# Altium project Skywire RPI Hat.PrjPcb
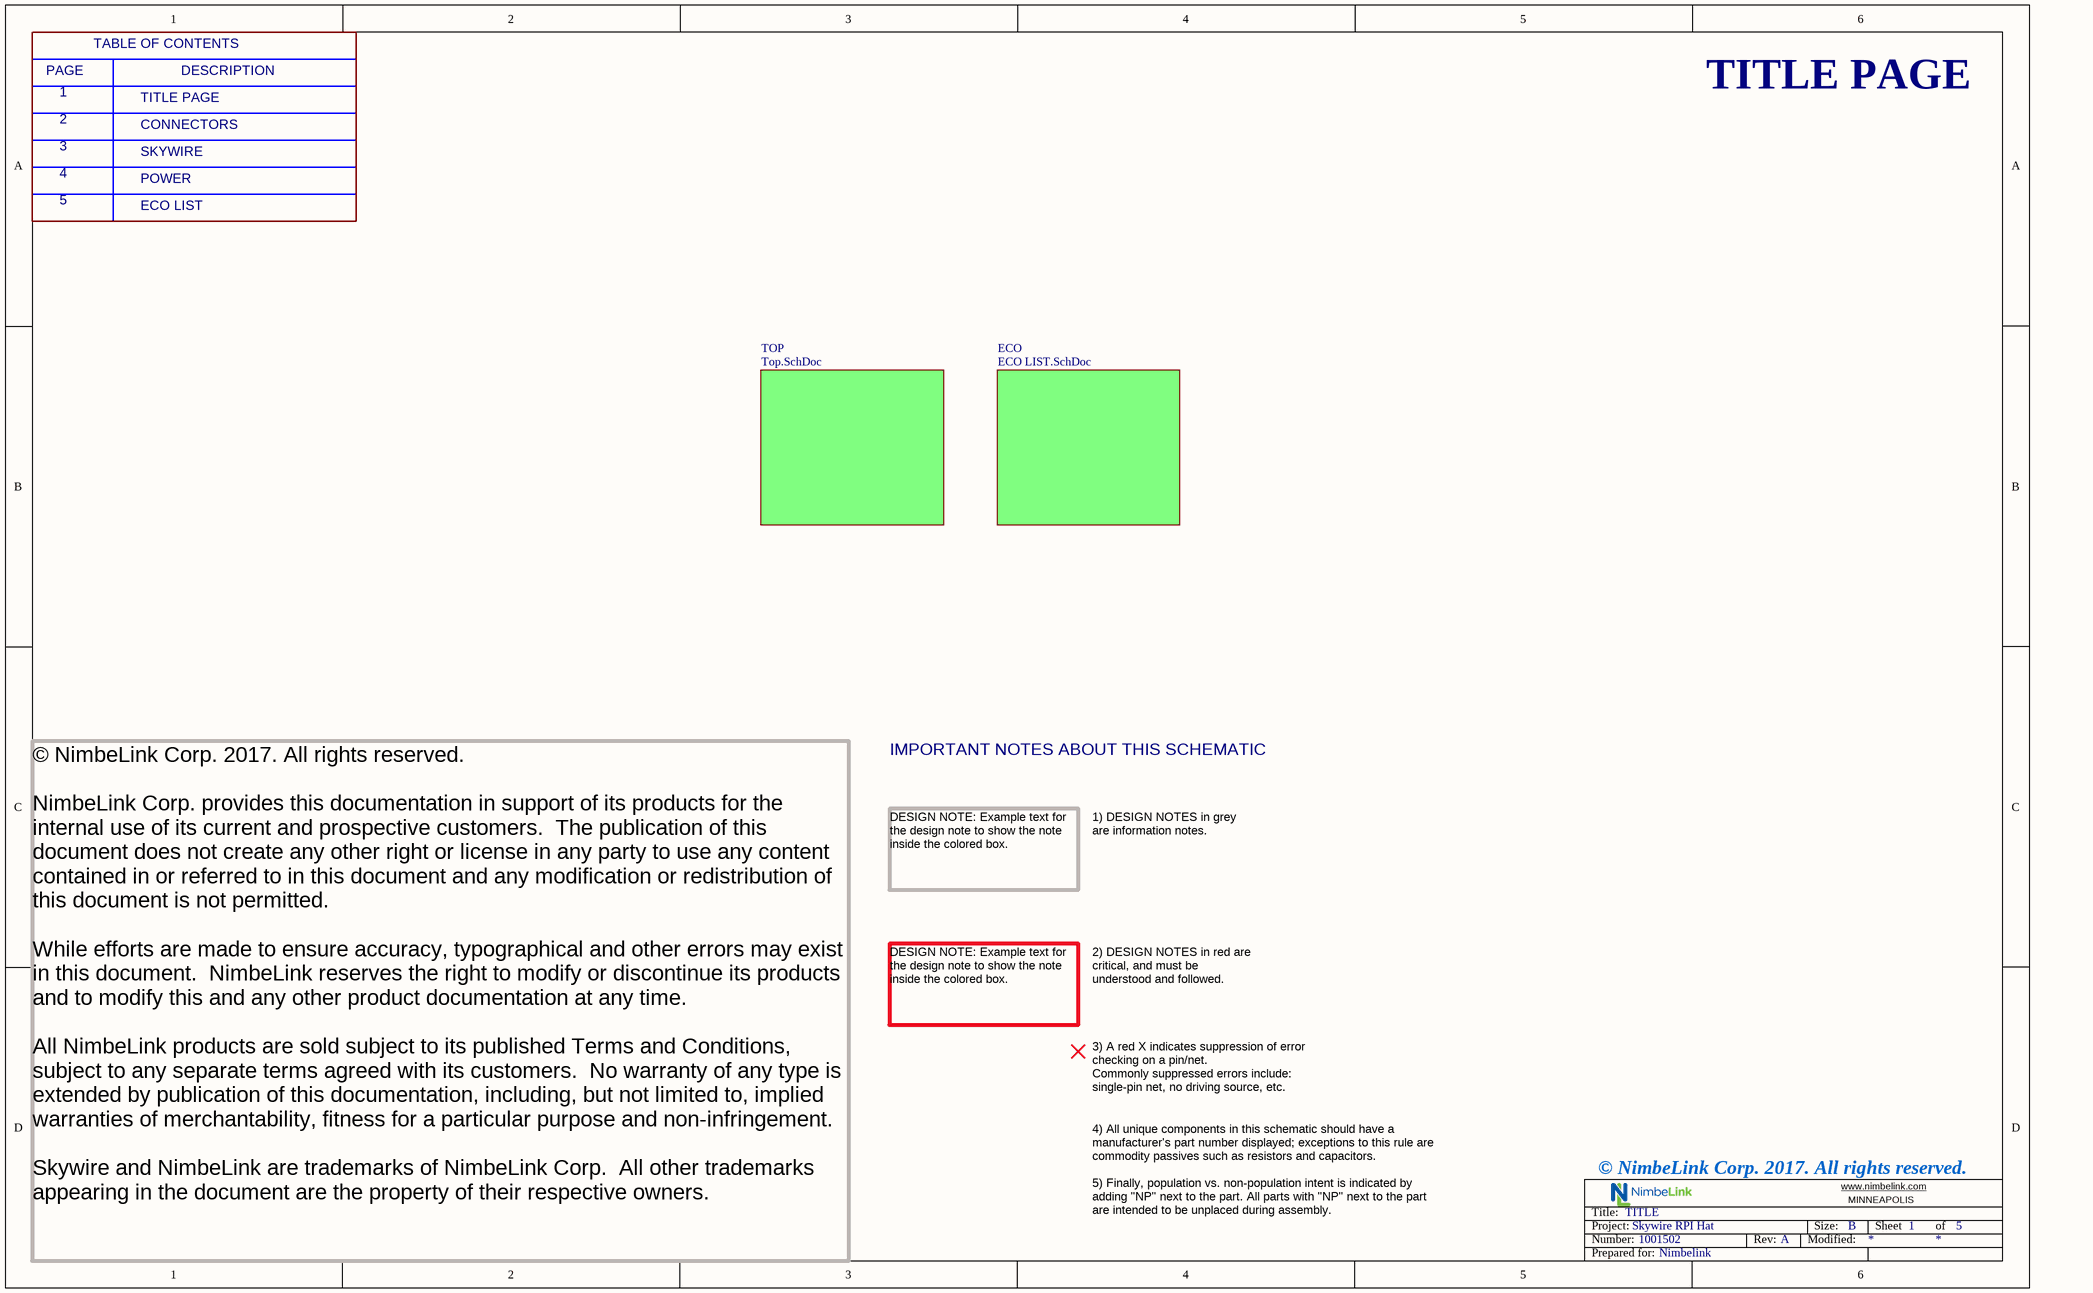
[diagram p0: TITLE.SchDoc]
NL_BILLING_CODE: Skywire RPI Hat; NL_SCH_PN: 1001502; NL_SCH_REV: A; NL_VERBOSE_CUST_NAME: Nimbelink
5 sheets, 73 parts. Net scope: flat (ports and power ports of the same name join across sheets).
Board file: RPI_Hat.PcbDoc
Sheets:
  TITLE.SchDoc
    TOP = Top.SchDoc
      Skywire = Skywire.SchDoc
      Power = Power.SchDoc
    ECO = ECO LIST.SchDoc

## Sheet TITLE.SchDoc: TITLE
size B; DocumentNumber: 1; SheetNumber: 1; SheetTotal: 5

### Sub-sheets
ECO = ECO LIST.SchDoc: no entries
TOP = Top.SchDoc: no entries

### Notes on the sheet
- PAGE
- 1
- TABLE OF CONTENTS
- TITLE PAGE
- DESCRIPTION
- 2
- 3
- CONNECTORS
- SKYWIRE
- 4
- 5
- ECO LIST
- POWER
- IMPORTANT NOTES ABOUT THIS SCHEMATIC
- DESIGN NOTE: Example text for the design note to show the note inside the colored box.
- 1) DESIGN NOTES in grey are information notes.
- 2) DESIGN NOTES in red are critical, and must be understood and followed.
- 3) A red X indicates suppression of error checking on a pin/net.
  Commonly suppressed errors include: single-pin net, no driving source, etc.
- © NimbeLink Corp. 2017. All rights reserved.
- 4) All unique components in this schematic should have a manufacturer's part number displayed; exceptions to this rule are commodity passives such as resistors and capacitors.
  5) Finally, population vs. non-population intent is indicated by adding "NP" next to the part. All parts with "NP" next to the part are intended to be unplaced during assembly.
- © NimbeLink Corp. 2017. All rights reserved.
  NimbeLink Corp. provides this documentation in support of its products for the internal use of its current and prospective customers.  The publication of this document does not create any other right or license in any party to use any content contained in or referred to in this document and any modification or redistribution of this document is not permitted.
  While efforts are made to ensure accuracy, typographical and other errors may exist in this document.  NimbeLink reserves the right to modify or discontinue its products and to modify this and any other product documentation at any time.
  All NimbeLink products are sold subject to its published Terms and Conditions, subject to any separate terms agreed with its customers.  No warranty of any type is extended by publication of this documentation, including, but not limited to, implied warranties of merchantability, fitness for a particular purpose and non-infringement.
  Skywire and NimbeLink are trademarks of NimbeLink Corp.  All other trademarks appearing in the document are the property of their respective owners.

## Sheet Top.SchDoc: TOP
size B; DocumentNumber: 2; SheetNumber: 2; SheetTotal: 5
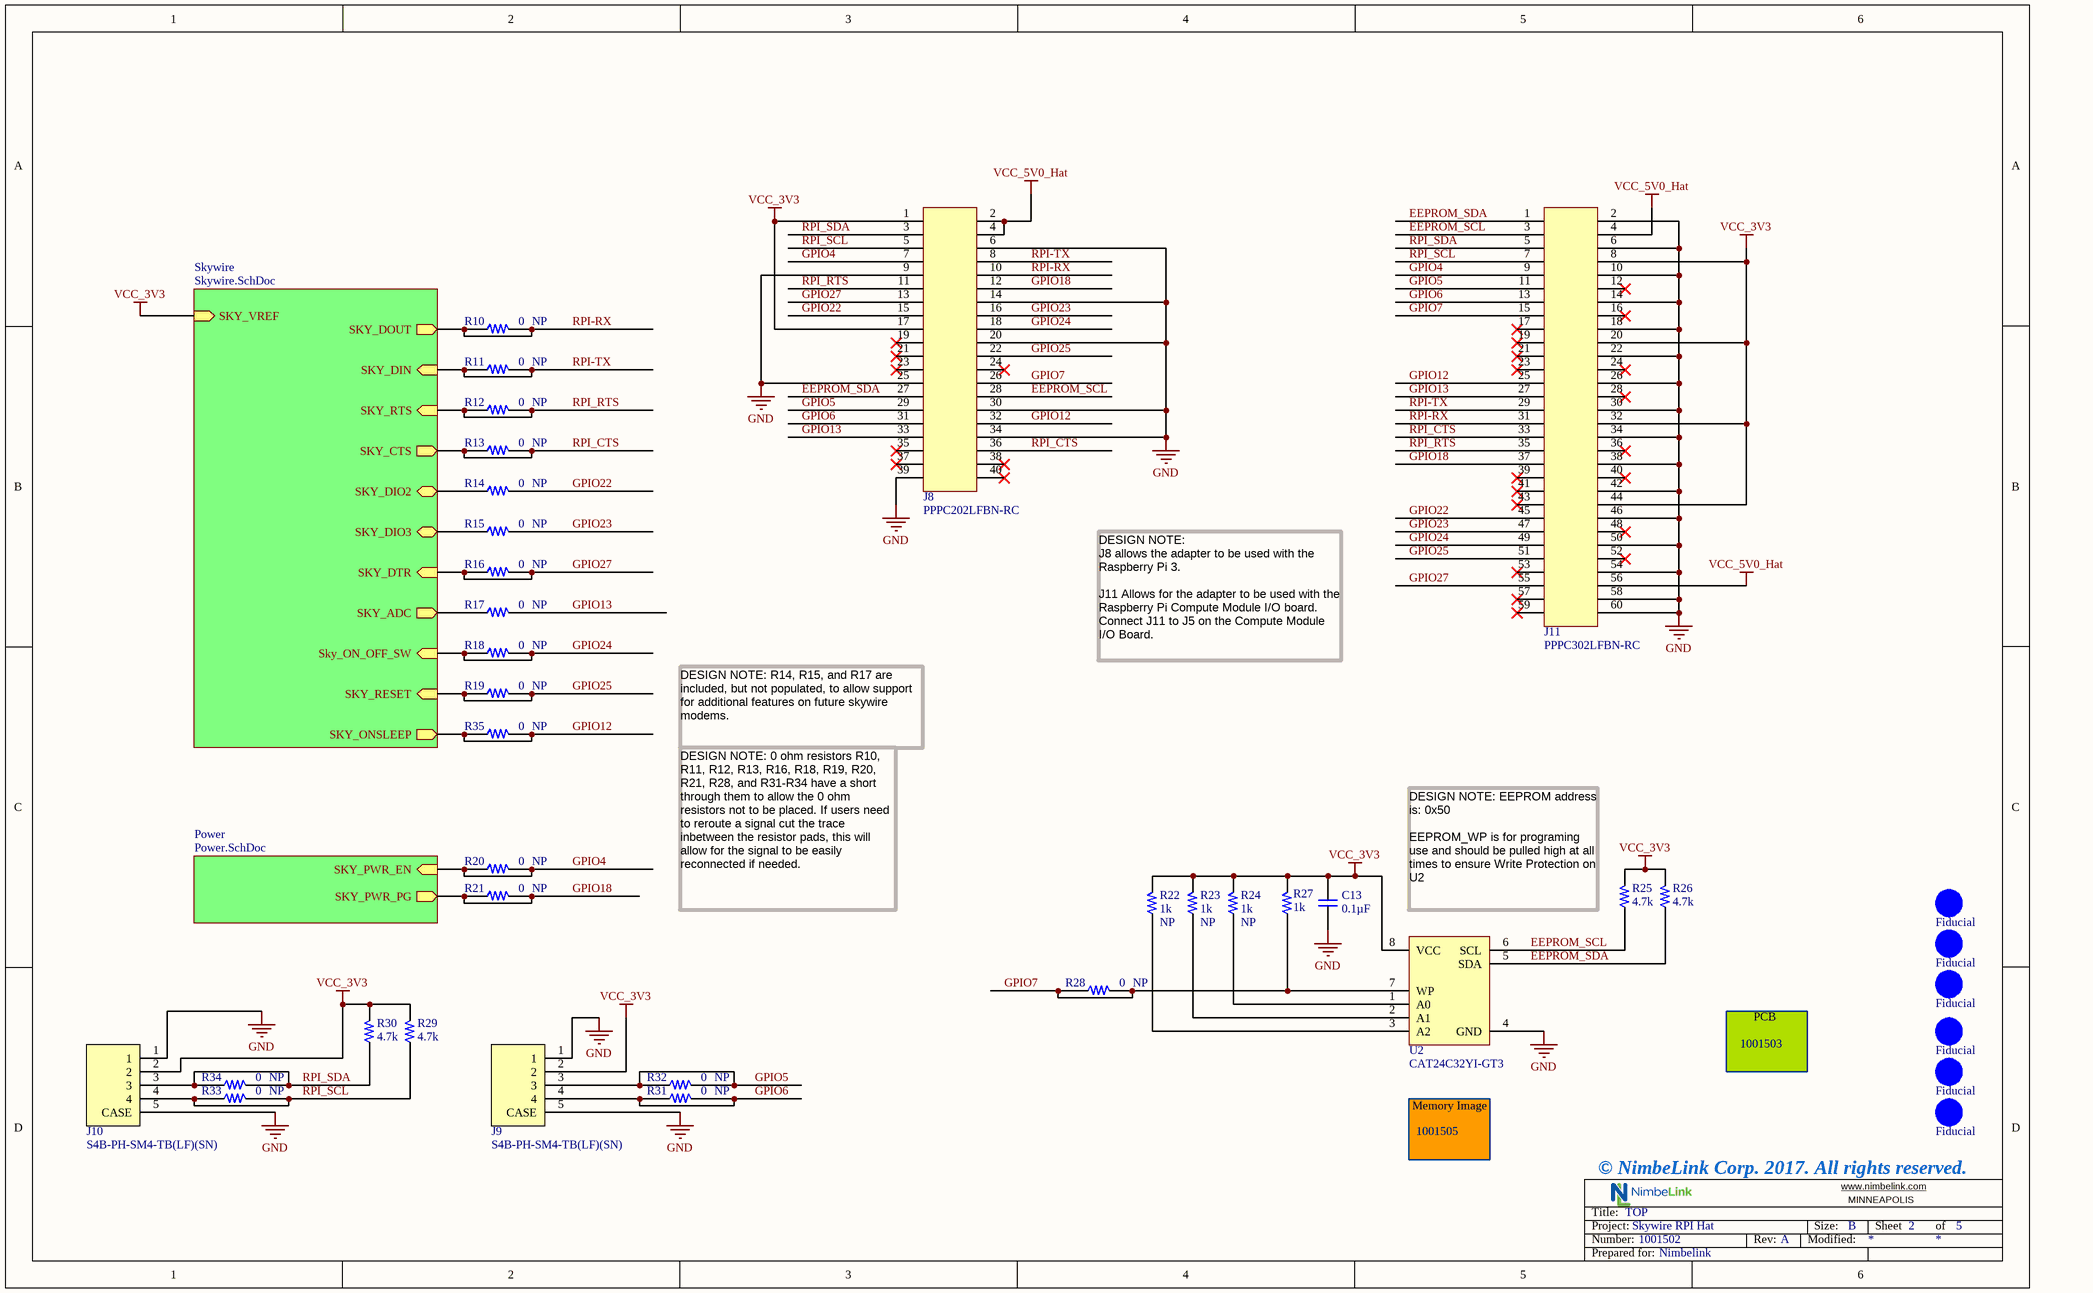
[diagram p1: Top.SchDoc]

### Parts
C13  Capacitance: 0.1µF  [0603]  (hidden comment: 1000755)
Fiducial1  Fiducial  [Fiducial 1mm]
Fiducial2  Fiducial  [Fiducial 1mm]
Fiducial3  Fiducial  [Fiducial 1mm]
Fiducial4  Fiducial  [Fiducial 1mm]
Fiducial5  Fiducial  [Fiducial 1mm]
Fiducial6  Fiducial  [Fiducial 1mm]
J8  1001252  [PPPC202LFBN-RC]  (value not drawn)
J9  1001260  [S4B-PH-SM4-TB(LF)(SN)]  (value not drawn)
J10  1001260  [S4B-PH-SM4-TB(LF)(SN)]  (value not drawn)
J11  1001253  [PPPC302LFBN-RC]  (value not drawn)
Memory_Image  Part_Number: 1001505  (hidden comment: Memory_Image)  (mechanical)
PCB  Part_Number: 1001503  (hidden comment: PCB)  (mechanical)
R10  Population: NP  [0603]  (hidden comment: 0)
R11  Population: NP  [0603]  (hidden comment: 0)
R12  Population: NP  [0603]  (hidden comment: 0)
R13  Population: NP  [0603]  (hidden comment: 0)
R14  Population: NP  [0603]  (hidden comment: 0)
R15  Population: NP  [0603]  (hidden comment: 0)
R16  Population: NP  [0603]  (hidden comment: 0)
R17  Population: NP  [0603]  (hidden comment: 0)
R18  Population: NP  [0603]  (hidden comment: 0)
R19  Population: NP  [0603]  (hidden comment: 0)
R20  Population: NP  [0603]  (hidden comment: 0)
R21  Population: NP  [0603]  (hidden comment: 0)
R22  Population: NP  Resistance_Ohms: 1k  [0603]
R23  Population: NP  Resistance_Ohms: 1k  [0603]
R24  Population: NP  Resistance_Ohms: 1k  [0603]
R25  Resistance_Ohms: 4.7k  [0603]  (hidden comment: 1000803)
R26  Resistance_Ohms: 4.7k  [0603]  (hidden comment: 1000803)
R27  Resistance_Ohms: 1k  [0603]
R28  Population: NP  [0603]  (hidden comment: 0)
R29  Resistance_Ohms: 4.7k  [0603]  (hidden comment: 1000803)
R30  Resistance_Ohms: 4.7k  [0603]  (hidden comment: 1000803)
R31  Population: NP  [0603]  (hidden comment: 0)
R32  Population: NP  [0603]  (hidden comment: 0)
R33  Population: NP  [0603]  (hidden comment: 0)
R34  Population: NP  [0603]  (hidden comment: 0)
R35  Population: NP  [0603]  (hidden comment: 0)
U2  .  [TSSOP8 4.4x3 CASE 948AL-01]  (value not drawn)

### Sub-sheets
Power = Power.SchDoc: SKY_PWR_EN (in), SKY_PWR_PG (out)
Skywire = Skywire.SchDoc: SKY_DOUT (out), SKY_DIN (in), SKY_RTS (in), SKY_CTS (out), Sky_ON_OFF_SW (in), SKY_DTR (in), SKY_VREF (in), SKY_DIO2 (bidir), SKY_DIO3 (bidir), SKY_ADC (out), SKY_RESET (in), SKY_ONSLEEP (out)

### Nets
GND: C13.2 J8.6 J8.9 J8.14 J8.20 J8.25 J8.30 J8.34 J8.39 J9.1 J9.5(CASE) J10.1 J10.5(CASE) J11.2 J11.6 J11.10 J11.14 J11.18 J11.22 J11.26 J11.30 J11.34 J11.38 J11.42 J11.46 J11.50 J11.54 J11.58 J11.60 U2.4(GND)
VCC_3V3: C13.1 J8.1 J8.17 J9.2 J10.2 J11.8 J11.20 J11.32 J11.44 R22.2 R23.2 R24.2 R25.2 R26.2 R27.2 R29.2 R30.2 U2.8(VCC) ; sheet Skywire/SKY_VREF
VCC_5V0_Hat: J8.2 J8.4 J11.4 J11.56
EEPROM_SCL: J8.28 J11.3 R25.1 U2.6(SCL)
EEPROM_SDA: J8.27 J11.1 R26.1 U2.5(SDA)
GPIO4: J8.7 J11.9 R20.1 R20.2 ; sheet Power/SKY_PWR_EN
GPIO5: J8.29 J9.3 J11.11 R32.1 R32.2
GPIO6: J8.31 J9.4 J11.13 R31.1 R31.2
GPIO7: J8.26 J11.15 R27.1 R28.1 R28.2 U2.7(WP)
GPIO12: J8.32 J11.25 R35.1 R35.2 ; sheet Skywire/SKY_ONSLEEP
GPIO13: J8.33 J11.27 R17.2
GPIO18: J8.12 J11.37 R21.1 R21.2 ; sheet Power/SKY_PWR_PG
GPIO22: J8.15 J11.45 R14.2
GPIO23: J8.16 J11.47 R15.2
GPIO24: J8.18 J11.49 R18.1 R18.2 ; sheet Skywire/Sky_ON_OFF_SW
GPIO25: J8.22 J11.51 R19.1 R19.2 ; sheet Skywire/SKY_RESET
GPIO27: J8.13 J11.55 R16.1 R16.2 ; sheet Skywire/SKY_DTR
RPI-RX: J8.10 J11.31 R10.1 R10.2 ; sheet Skywire/SKY_DOUT
RPI-TX: J8.8 J11.29 R11.1 R11.2 ; sheet Skywire/SKY_DIN
RPI_CTS: J8.36 J11.33 R13.1 R13.2 ; sheet Skywire/SKY_CTS
RPI_RTS: J8.11 J11.35 R12.1 R12.2 ; sheet Skywire/SKY_RTS
RPI_SCL: J8.5 J10.4 J11.7 R29.1 R33.1 R33.2
RPI_SDA: J8.3 J10.3 J11.5 R30.1 R34.1 R34.2
NetR14_1: R14.1 ; sheet Skywire/SKY_DIO2
NetR15_1: R15.1 ; sheet Skywire/SKY_DIO3
NetR17_1: R17.1 ; sheet Skywire/SKY_ADC
NetR22_1: R22.1 U2.3(A2)
NetR23_1: R23.1 U2.2(A1)
NetR24_1: R24.1 U2.1(A0)

Not connected (* = marked no-connect by the designer): J8 19* 21* 23* 24* 35* 37* 38* 40*; J11 12* 16* 17* 19* 21* 23* 24* 28* 36* 39* 40* 41* 43* 48* 52* 53* 57* 59*

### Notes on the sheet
- DESIGN NOTE:
  J8 allows the adapter to be used with the Raspberry Pi 3.
  J11 Allows for the adapter to be used with the Raspberry Pi Compute Module I/O board. Connect J11 to J5 on the Compute Module I/O Board.
- DESIGN NOTE: R14, R15, and R17 are included, but not populated, to allow support for additional features on future skywire modems.
- DESIGN NOTE: 0 ohm resistors R10, R11, R12, R13, R16, R18, R19, R20, R21, R28, and R31-R34 have a short through them to allow the 0 ohm resistors not to be placed. If users need to reroute a signal cut the trace inbetween the resistor pads, this will allow for the signal to be easily reconnected if needed.
- DESIGN NOTE: EEPROM address is: 0x50
  EEPROM_WP is for programing use and should be pulled high at all times to ensure Write Protection on U2
- © NimbeLink Corp. 2017. All rights reserved.

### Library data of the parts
C13 = 1000755: Capacitor, 0.1 uF, 16V, 5%, X7R, 0603; Manufacturer1: Samsung Electro-Mechanics America, Inc; Manufacturer_Part_Number1: CL10B104JO8NNNC; Item_Phase: Production; Capacitor_Type: Ceramic; Mounting_Type: Surface Mount; Operating_Temperature: -55°C ~ 125°C; Thickness_Max: 0.035" (0.90mm)
Fiducial1-Fiducial6 = Fiducial: Fiducial, 1mm; Population: NP
J8 = 1001252: Connector, Header, Female, 2.54mm, 20x2, TH; Manufacturer1: Sullins Connector Solutions; Item_Phase: Production; Contact_Finish: Gold; Contact_Type: Female Socket; Current_Rating: 3A; Fastening_Type: Push-Pull; Mounting_Type: Through Hole; Number_of_Pins: 40; Number_of_Rows: 2; Operating_Temperature: -40C ~ +105C; Pitch: 0.100 (2.54mm)"; Voltage_Rating: 250V
J9 J10 = 1001260: Connector, Header, Male, 2.00mm, 4x1, Right Angle, SMD; Manufacturer1: JST Sales America Inc; Pitch: 0.079 (2.00mm)"; Item_Phase: Production; Connector_Type: Header, Shrouded; Contact_Finish: Tin; Contact_Type: Male Pin; Fastening_Type: Detent Lock; Mounting_Type: Surface Mount Right Angle; Number_of_Pins: 4; Number_of_Positions_Loaded: All; Number_of_Rows: 1
J11 = 1001253: Connector, Header, Female, 2.54mm, 30x2, TH; Manufacturer1: Sullins Connector Solutions; Item_Phase: Production; Contact_Finish: Gold; Contact_Type: Female Socket; Current_Rating: 3A; Mounting_Type: Through Hole; Number_of_Pins: 60; Number_of_Rows: 2; Operating_Temperature: -40C ~ +105C; Pitch: 0.100 (2.54mm)"; Voltage_Rating: 250V
Memory_Image = Memory_Image: Memory Image
PCB = PCB: PCB Part Number
R10-R21 R28 R31-R35 = 1000666: Resistor, 0, 1/10W, 0603; Manufacturer1: Panasonic Electronic Components; Manufacturer_Part_Number1: ERJ-3GEY0R00V; Item_Phase: Production; Mounting_Type: Surface Mount; Number_of_Terminations: 2; Operating_Temperature: -55°C ~ 155°C; Power: 0.1W, 1/10W; Resistor_Package: 0603 (1608 Metric); Tolerance: Jumper
R22-R24 R27 = 1000590: Resistor, 1K, 1%, 1/10W, 0603; Manufacturer1: Panasonic Electronic Components; Manufacturer_Part_Number1: ERJ-3EKF1001V; Item_Phase: Production; Mounting_Type: Surface Mount; Number_of_Terminations: 2; Operating_Temperature: -55°C ~ 155°C; Power: 0.1W, 1/10W; Resistor_Package: 0603 (1608 Metric); Temperature_Coefficient: ±100ppm/°C
R25 R26 R29 R30 = 1000803: Resistor, 4.7K, 1%, 1/10W, 0603; Manufacturer1: Samsung Electro-Mechanics America, Inc; Manufacturer_Part_Number1: RC1608F472CS; Item_Phase: Production; Mounting_Type: Surface Mount; Number_of_Terminations: 2; Operating_Temperature: -55°C ~ 155°C; Power: 0.1W, 1/10W; Resistor_Package: 0603 (1608 Metric); Temperature_Coefficient: ±100ppm/°C
U2 = 1001385: IC, EEPROM, I2C, 32Kb, 400KHz, 1.7V-5.5V, 8-TSSOP; Manufacturer1: ON Semiconductor; Item_Phase: Preliminary; Current_Supply: 2 mA; Mounting_Type: Surface Mount; Operating_Temperature: -40°C ~ 85°C; Voltage_Supply_Max: 5.5V; Voltage_Supply_Min: 1.7V; Voltage_Supply_Typical: 3.3V

## Sheet Skywire.SchDoc: SKYWIRE
size B; DocumentNumber: 3; SheetNumber: 3; SheetTotal: 5
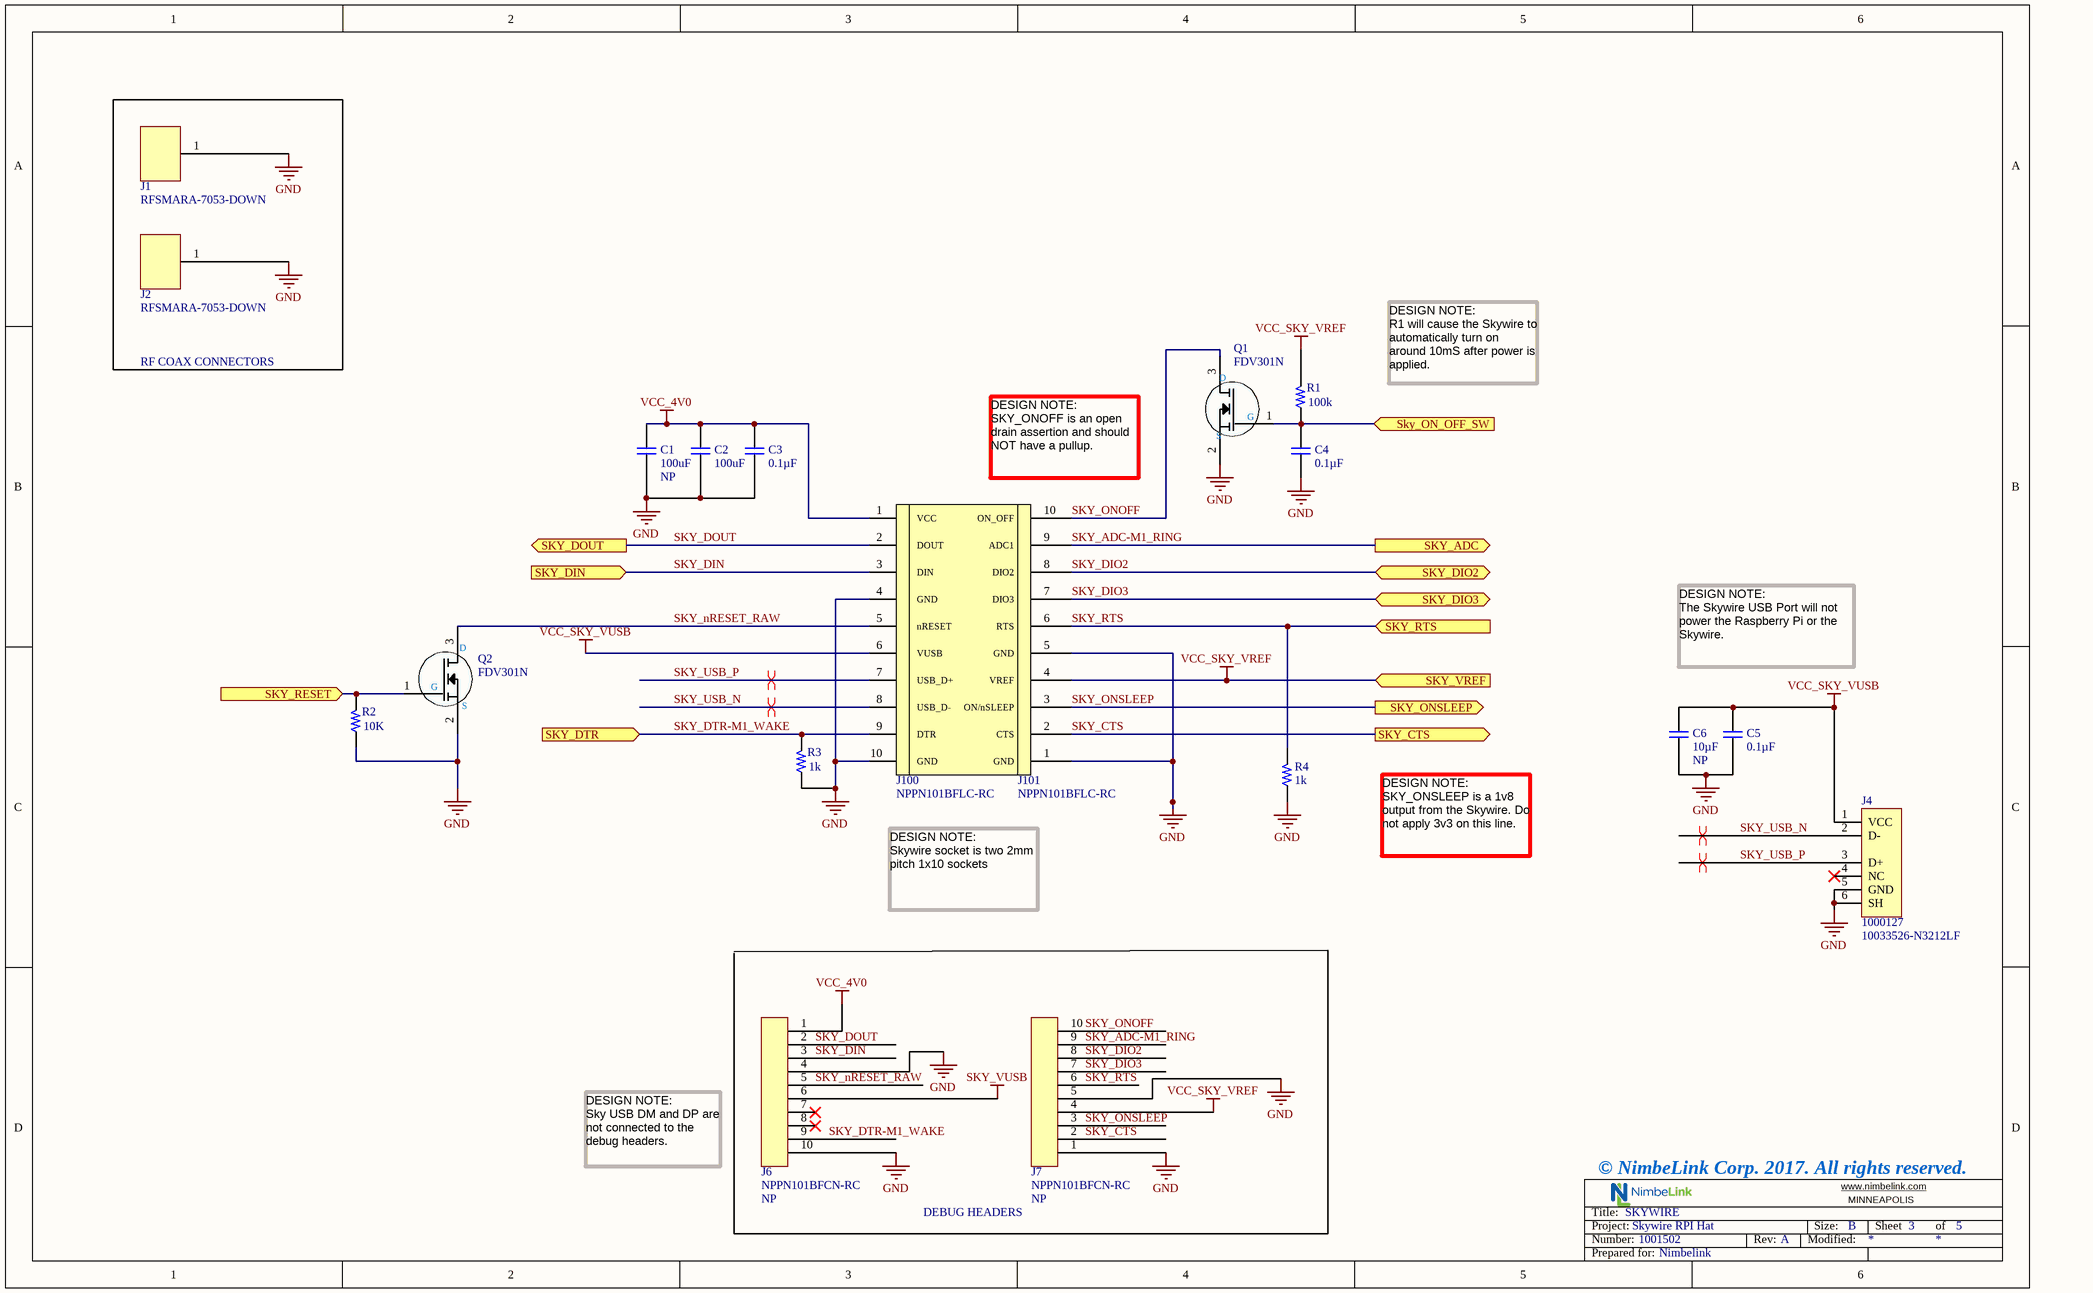
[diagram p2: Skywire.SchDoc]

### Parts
C1  Population: NP  Capacitance: 100uF  [CAPC3225X25N_1210]  (hidden comment: 1001241)
C2  Capacitance: 100uF  [CAPC3225X25N_1210]  (hidden comment: 1001241)
C3  Capacitance: 0.1µF  [0603]  (hidden comment: 1000755)
C4  Capacitance: 0.1µF  [0603]  (hidden comment: 1000755)
C5  Capacitance: 0.1µF  [0603]  (hidden comment: 1000755)
C6  Capacitance: 10µF  Population: NP  [0805]  (hidden comment: 1000780)
J1  UFL to SMA  [UFL TO SMA]  (value not drawn)
J2  UFL to SMA  [UFL TO SMA]  (value not drawn)
J4  Part_Number: 1000127  [10033526-N3212LF]  (hidden comment: USB MINI B)
J6  Population: NP  [NPPN101BFCN-RC]  (hidden comment: 1000864)
J7  Population: NP  [NPPN101BFCN-RC]  (hidden comment: 1000864)
J100  1000865  [NPPN101BFLC-RC]  (value not drawn)
J101  1000865  [NPPN101BFLC-RC]  (value not drawn)
Q1  1000512  [SOT95P300X115-3N]  (value not drawn)
Q2  1000512  [SOT95P300X115-3N]  (value not drawn)
R1  100K  [0603]
R2  10K  [0603]
R3  Resistance_Ohms: 1k  [0603]
R4  Resistance_Ohms: 1k  [0603]

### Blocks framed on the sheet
RF COAX CONNECTORS: J1 J2
DEBUG HEADERS: J6 J7

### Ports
SKY_ADC (out), SKY_CTS (out), SKY_DIN (in), SKY_DIO2 (bidir), SKY_DIO3 (bidir), SKY_DOUT (out), SKY_DTR (in), Sky_ON_OFF_SW (in), SKY_ONSLEEP (out), SKY_RESET (in), SKY_RTS (in), SKY_VREF (in)

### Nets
GND: C1.2 C2.2 C3.2 C4.2 C5.2 C6.2 J1.1 J2.1 J4.5(GND) J4.6(SH) J6.4 J6.10 J7.1 J7.5 J100.4 J100.10 J101.1 J101.5 Q1.2(S) Q2.2(S) R2.1 R3.1 R4.1
SKY_VUSB: J6.6
VCC_4V0: C1.1 C2.1 C3.1 J6.1 J100.1
VCC_SKY_VREF: J7.4 J101.4 R1.2 ; port SKY_VREF
VCC_SKY_VUSB: C5.1 C6.1 J4.1(VCC) J100.6
SKY_ADC-M1_RING: J7.9 J101.9 ; port SKY_ADC
SKY_CTS: J7.2 J101.2 ; port SKY_CTS
SKY_DIN: J6.3 J100.3 ; port SKY_DIN
SKY_DIO2: J7.8 J101.8 ; port SKY_DIO2
SKY_DIO3: J7.7 J101.7 ; port SKY_DIO3
SKY_DOUT: J6.2 J100.2 ; port SKY_DOUT
SKY_DTR-M1_WAKE: J6.9 J100.9 R3.2 ; port SKY_DTR
SKY_nRESET_RAW: J6.5 J100.5 Q2.3(D)
SKY_ONOFF: J7.10 J101.10 Q1.3(D)
SKY_ONSLEEP: J7.3 J101.3 ; port SKY_ONSLEEP
SKY_RTS: J7.6 J101.6 R4.2 ; port SKY_RTS
SKY_USB_N: J4.2(D-) J100.8
SKY_USB_P: J4.3(D+) J100.7
NetC4_1: C4.1 Q1.1(G) R1.1 ; port Sky_ON_OFF_SW
NetQ2_1: Q2.1(G) R2.2 ; port SKY_RESET

Not connected (* = marked no-connect by the designer): J4 4(NC)*; J6 7* 8*

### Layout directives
differential pair: SKY_USB_N, SKY_USB_P
differential pair; net class DIFF90: SKY_USB_N, SKY_USB_P

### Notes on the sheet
- DESIGN NOTE:
  R1 will cause the Skywire to automatically turn on around 10mS after power is applied.
- (near J101) DESIGN NOTE:
  SKY_ONOFF is an open drain assertion and should NOT have a pullup.
- (near J100) VCC
- (near J100) DOUT
- (near J101) ON_OFF
- (near J101) ADC1
- (near J100) DIN
- (near J100) GND
- (near J100) nRESET
- (near J101) DIO3
- (near J101) DIO2
- (near J101) RTS
- (near J100) VUSB
- (near J100) USB_D+
- (near J101) VREF
- (near J101) GND
- DESIGN NOTE:
  The Skywire USB Port will not power the Raspberry Pi or the Skywire.
- (near J100) USB_D-
- (near J100) DTR
- (near J101) ON/nSLEEP
- (near J101) CTS
- DESIGN NOTE:
  Skywire socket is two 2mm pitch 1x10 sockets
- DESIGN NOTE:
  SKY_ONSLEEP is a 1v8 output from the Skywire. Do not apply 3v3 on this line.
- DESIGN NOTE:
  Sky USB DM and DP are not connected to the debug headers.
- © NimbeLink Corp. 2017. All rights reserved.

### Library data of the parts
C1 C2 = 1001241: Capacitor. 100uF, 10V, 20%, X5R, 1210; Manufacturer1: Taiyo Yuden; Tolerance: +/- 20%; Item_Phase: Production; Capacitor_Type: Ceramic; Mounting_Type: Surface Mount; Operating_Temperature: -55C ~ +85C; Thickness_Max: 0.106 (2.70mm)"
C3-C5 = 1000755: as C13 on sheet Top
C6 = 1000780: Capacitor, 10 uF, 25V, 10%, X5R, 0805; Manufacturer1: Samsung Electro-Mechanics America, Inc; Manufacturer_Part_Number1: CL21A106KAYNNNE; Item_Phase: Production; Capacitor_Type: Ceramic; Mounting_Type: Surface Mount; Operating_Temperature: -55°C ~ 85°C; Thickness_Max: 0.057" (1.45mm)
J1 J2 = 1000732: Connector, ANT, UFL to PCB Mount SMA, UFL Down, 53mm, TH; Manufacturer1: ROHO COMMUNICATION TECHNOLOGY CO. Ltd; Item_Phase: Production; Mounting_Type: Other
J4 = 1000127: Connector, USB, Mini B, Right Angle, SMD; Manufacturer1: Amphenol; Gender: Receptacle; Item_Phase: Production; Connector_Type: USB - mini B; Mounting_Type: Surface Mount Right Angle Horizontal; Number_of_Pins: 5
J6 J7 = 1000864: Connector, Header, Female, 2.00mm, 10x1, TH; Manufacturer1: Sullins Connector Solutions; Pitch: 0.079" (2.00mm); Item_Phase: Production; Contact_Finish: Gold; Contact_Type: Female Socket; Mounting_Type: Through Hole; Number_of_Positions: 10; Number_of_Positions_Loaded: All; Number_of_Rows: 1
J100 J101 = 1000865: Connector, Female, 2.00mm, 10x1, SMD, Left Oriented; Manufacturer1: Sullins Connector Solutions; Item_Phase: Production; Connector_Type: Header; Contact_Finish: Gold; Contact_Type: Female Socket; Current_Rating: 2A; Fastening_Type: Push-Pull; Header_Orientation: Vertical; Insertion_Removal_Method: Push In / Pull Out; Mounting_Type: Surface Mount; Number_of_Pins: 10; Number_of_Rows: 1; Operating_Temperature: -40°C ~ 105°C; Pitch: 0.079" (2.00mm); Voltage_Rating: 150V
Q1 Q2 = 1000512: Transistor, MOSFET, N-CH, 25V, 0.220mA, SOT-23-3; Manufacturer1: ON Semiconductor; Item_Phase: Production; Mounting_Type: Surface Mount; Transistor_Type: NCH - FET
R1 = 1000799: Resistor, 100K, 1%, 1/10W, 0603; Manufacturer1: Samsung Electro-Mechanics America, Inc; Manufacturer_Part_Number1: RC1608F104CS; Item_Phase: Production; Mounting_Type: Surface Mount; Number_of_Terminations: 2; Power: 0.1W, 1/10W; Resistor_Package: 0603 (1608 Metric); Temperature_Coefficient: ±100ppm/°C
R2 = 1000591: Resistor, 10K, 1%, 1/10W, 0603; Manufacturer1: Panasonic Electronic Components; Manufacturer_Part_Number1: ERJ-3EKF1002V; Item_Phase: Production; Mounting_Type: Surface Mount; Operating_Temperature: - 55 C to + 155 C; Power: 0.1W, 1/10W; Resistor_Package: 0603 (1608 Metric); Temperature_Coefficient: 100 PPM / C
R3 R4 = 1000590: as R22 on sheet Top

## Sheet Power.SchDoc: POWER
size B; DocumentNumber: 4; SheetNumber: 4; SheetTotal: 5
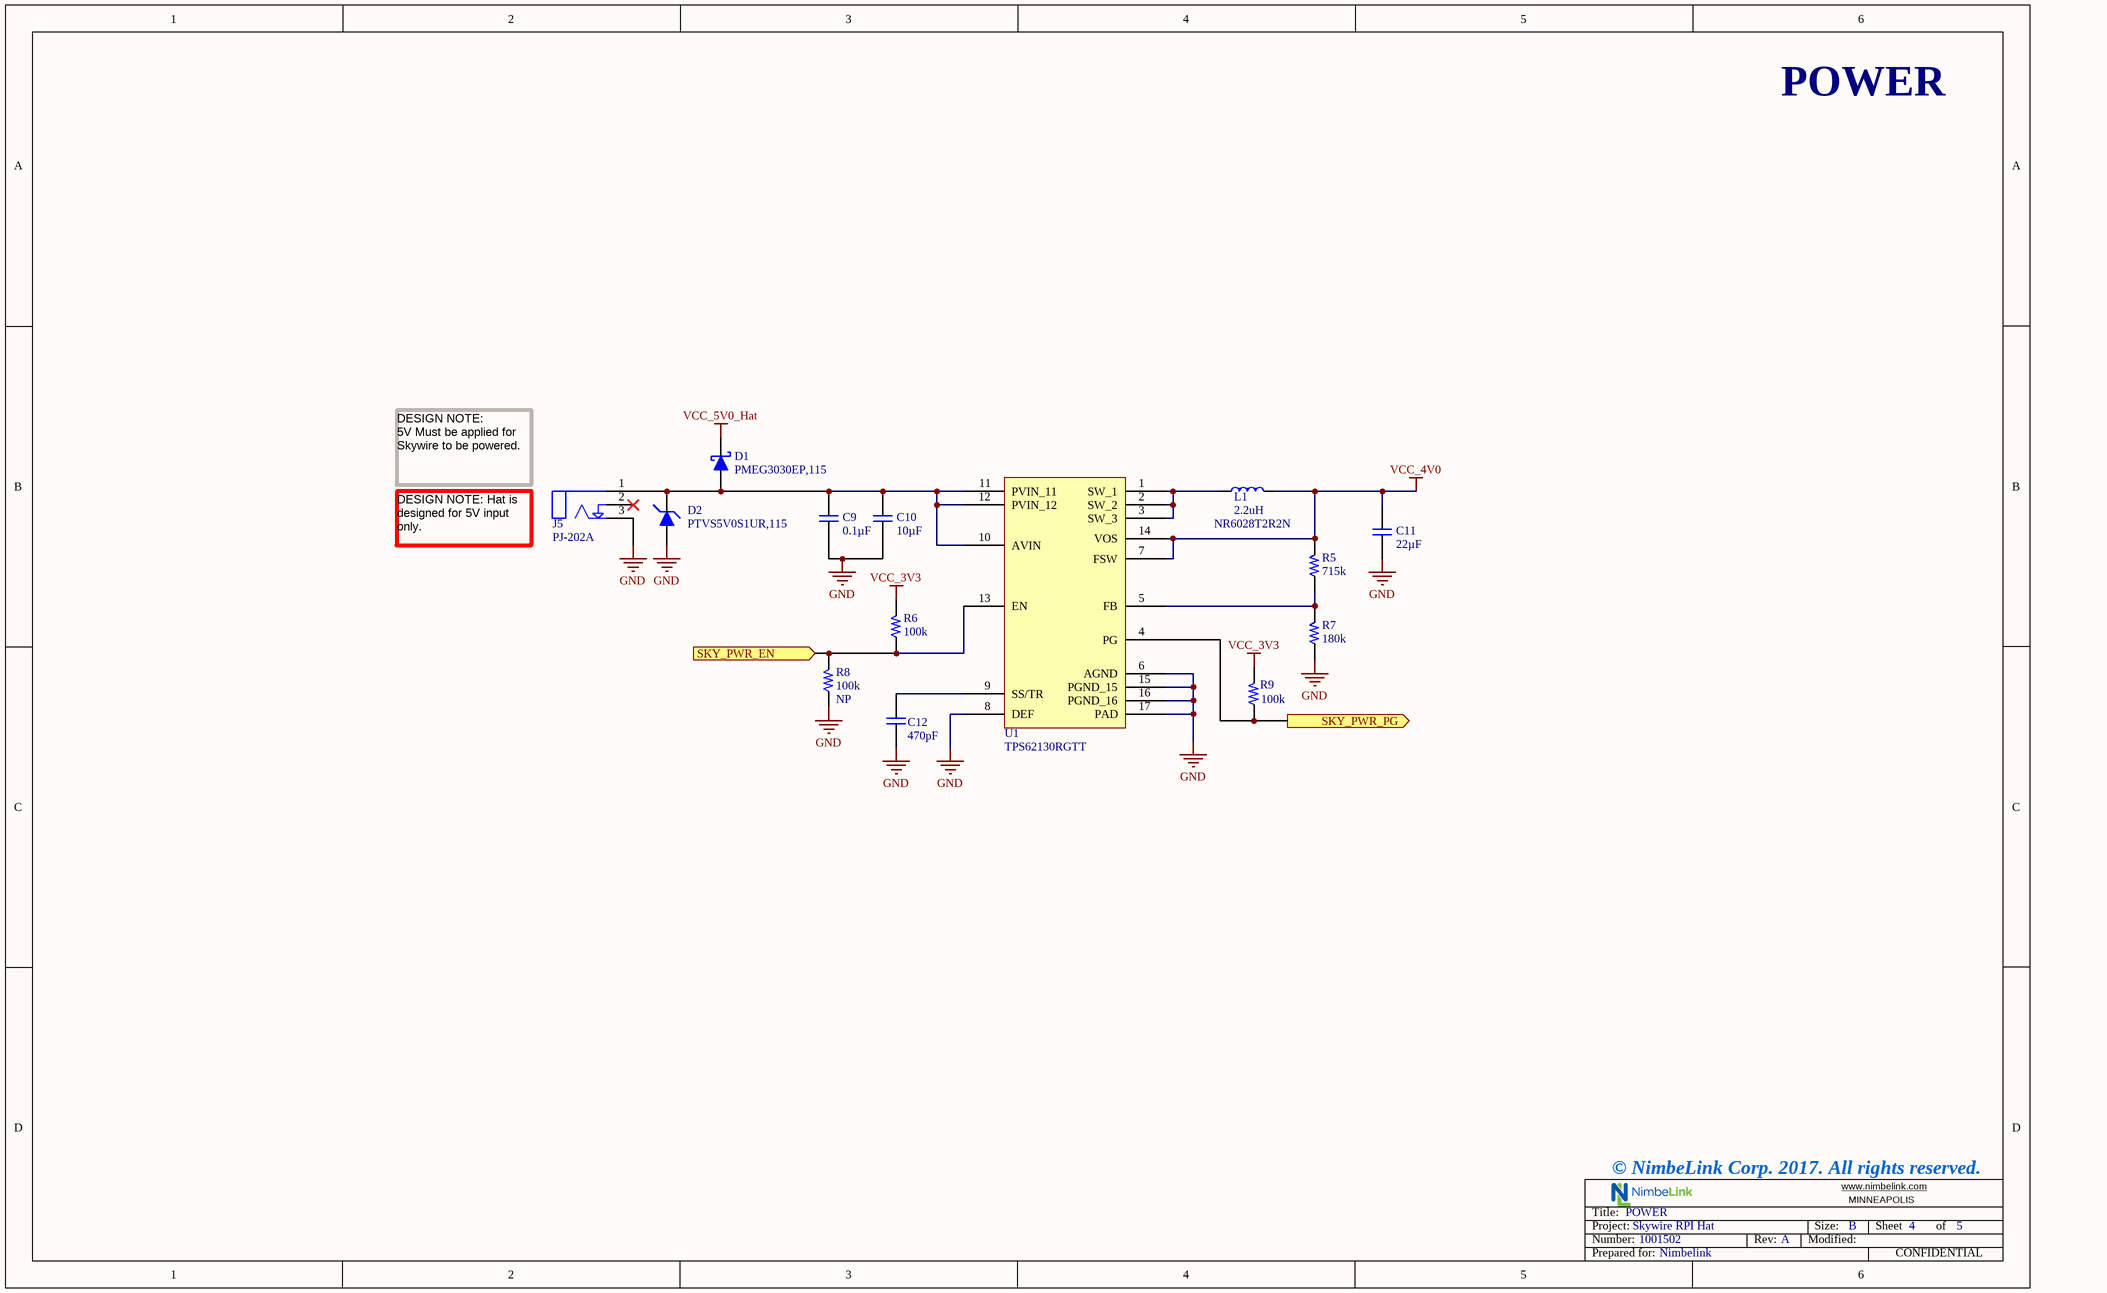
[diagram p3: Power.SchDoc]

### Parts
C9  Capacitance: 0.1µF  [0603]  (hidden comment: 1000755)
C10  Capacitance: 10µF  [0805]  (hidden comment: 1000780)
C11  Capacitance: 22µF  [0603]  (hidden comment: C, 22 uF, 25V, 20%, X5R, 0603 CER)
C12  Capacitance: 470pF  [0603]  (hidden comment: C, 470 pF, 50V, 5%, C0G/NP0, 0603 CER)
D1  1001261  [SOD128]  (value not drawn)
D2  1000501  [SOD123W]  (value not drawn)
J5  1000221  [PJ-202A]  (value not drawn)
L1  Inductance: 2.2uH  [NR6028]  (hidden comment: 1001263)
R5  715K  [0603]
R6  100K  [0603]
R7  Resistance_Ohms: 180k  [0603]  (hidden comment: 1001234)
R8  Population: NP  [0603]  (hidden comment: 100K)
R9  100K  [0603]
U1  TPS62130RGTT  [QFN50P300X300X100_HS-17N]

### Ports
SKY_PWR_EN (in), SKY_PWR_PG (out)

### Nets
GND: C9.2 C10.2 C11.2 C12.1 D2.A J5.3 R7.1 R8.1 U1.6(AGND) U1.8(DEF) U1.15(PGND_15) U1.16(PGND_16) U1.17(PAD)
VCC_3V3: R6.2 R9.2
VCC_4V0: C11.1 L1.2 R5.2 U1.7(FSW) U1.14(VOS)
VCC_5V0_Hat: D1.K
NetC9_1: C9.1 C10.1 D1.A D2.K J5.1 U1.10(AVIN) U1.11(PVIN_11) U1.12(PVIN_12)
NetC12_2: C12.2 U1.9(SS/TR)
NetL1_1: L1.1 U1.1(SW_1) U1.2(SW_2) U1.3(SW_3)
NetR5_1: R5.1 R7.2 U1.5(FB)
NetR6_1: R6.1 R8.2 U1.13(EN) ; port SKY_PWR_EN
NetR9_1: R9.1 U1.4(PG) ; port SKY_PWR_PG

Not connected (* = marked no-connect by the designer): J5 2*

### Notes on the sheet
- POWER
- DESIGN NOTE:
  5V Must be applied for Skywire to be powered.
- DESIGN NOTE: Hat is designed for 5V input only.
- © NimbeLink Corp. 2017. All rights reserved.

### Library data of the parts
C9 = 1000755: as C13 on sheet Top
C10 = 1000780: as C6 on sheet Skywire
C11 = 1000932: Capacitor, 22 uF, 25V, 20%, X5R, 0603; Manufacturer1: TDK Corporation; Manufacturer_Part_Number1: C1608X5R1A226M080AC; Item_Phase: Production; Capacitor_Type: Ceramic; Mounting_Type: Surface Mount; Operating_Temperature: -55°C ~ 85°C; Thickness_Max: 0.035" (0.90mm); Voltage_Rating: 10V
C12 = 1000777: Capacitor, 470 pF, 50V, 5%, C0G/NP0, 0603; Manufacturer1: Samsung Electro-Mechanics America, Inc; Manufacturer_Part_Number1: CL10C471JB8NCNC; Item_Phase: Production; Capacitor_Type: Ceramic; Mounting_Type: Surface Mount; Operating_Temperature: -55°C ~ 125°C; Temperature_Coefficient: C0G, NP0; Thickness_Max: 0.035" (0.90mm)
D1 = 1001261: Diode, Schottky, 30V, 3A, 0.360 Vf, SOD-128; Manufacturer1: NXP Semiconductors; Item_Phase: Production; Current_Reverse_Leakage_at_Vref: 5mA @ 30V; Mounting_Type: Surface Mount; Operating_Temperature: 150°C (Max); Voltage_Forward_VF_Max_at_I_Forward: 360mV @ 3A
D2 = 1000501: Diode, TVS, Unidirectional, 5V, 43.5A, SOD-123W; Manufacturer1: NXP Semiconductors; Item_Phase: Production; Diode_Type: Zener; Mounting_Type: Surface Mount; Operating_Temperature: -55°C ~ 150°C (TA)
J5 = 1000221: Connector, Barrel, 24V, 2.5A, 2.1mm ID, 5.5mm OD; Manufacturer1: CUI Inc; Gender: Male; Item_Phase: Production; Connector_Type: Jack; Mounting_Type: Through Hole; Operating_Temperature: -25°C ~ 85°C; Voltage_Rating: 16VDC
L1 = 1001263: Inductor, 2.2uH, 3.7A, 30%, 26mOhm, 6.00x6.00mm; Manufacturer1: Taiyo Yuden; Shielding: Shielded; Item_Phase: Production; Current_Saturation: 4.2A; DC_Resistance: 26 mOhm Max; Frequency_Self_Resonant: 68MHz; Frequency_Test: 100kHz; Mounting_Type: Surface Mount; Operating_Temperature: -25°C ~ 120°C; Inductor_Type: Wirewound
R5 = 1000656: Resistor, 715K, 1%, 1/10W, 0603; Manufacturer1: Panasonic Electronic Components; Manufacturer_Part_Number1: ERJ-3EKF7153V; Item_Phase: Production; Mounting_Type: Surface Mount; Number_of_Terminations: 2; Operating_Temperature: -55°C ~ 155°C; Power: 0.1W, 1/10W; Resistor_Package: 0603 (1608 Metric); Temperature_Coefficient: ±100ppm/°C
R6 R8 R9 = 1000799: as R1 on sheet Skywire
R7 = 1001234: Resistor, 180K, 1%, 1/10W, 0603; Manufacturer1: Yageo; Manufacturer_Part_Number1: RC0603FR-07180KL; Item_Phase: Production; Mounting_Type: Surface Mount; Number_of_Terminations: 2; Operating_Temperature: -55°C ~ 155°C; Power: 0.1W, 1/10W; Resistor_Package: 0603 (1608 Metric); Temperature_Coefficient: ±100ppm/°C
U1 = 1001036: IC, Buck, ADJ, 3V-17V , 3A, QFN; Manufacturer1: Texas Instruments; Item_Phase: Production; Mounting_Type: Surface Mount; Operating_Temperature: -40°C ~ 85°C; Output_Type: Adjustable

## Sheet ECO LIST.SchDoc: ECO LIST
size C; DocumentNumber: 5; SheetNumber: 5; SheetTotal: 5
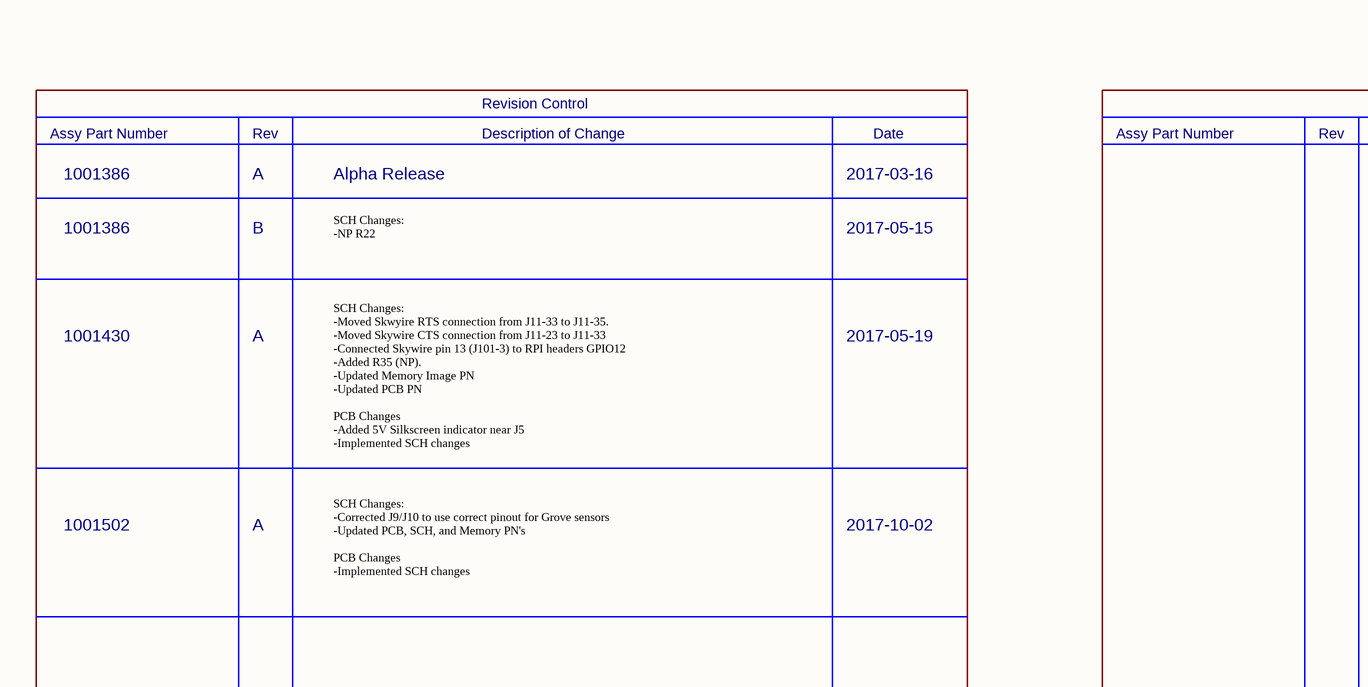
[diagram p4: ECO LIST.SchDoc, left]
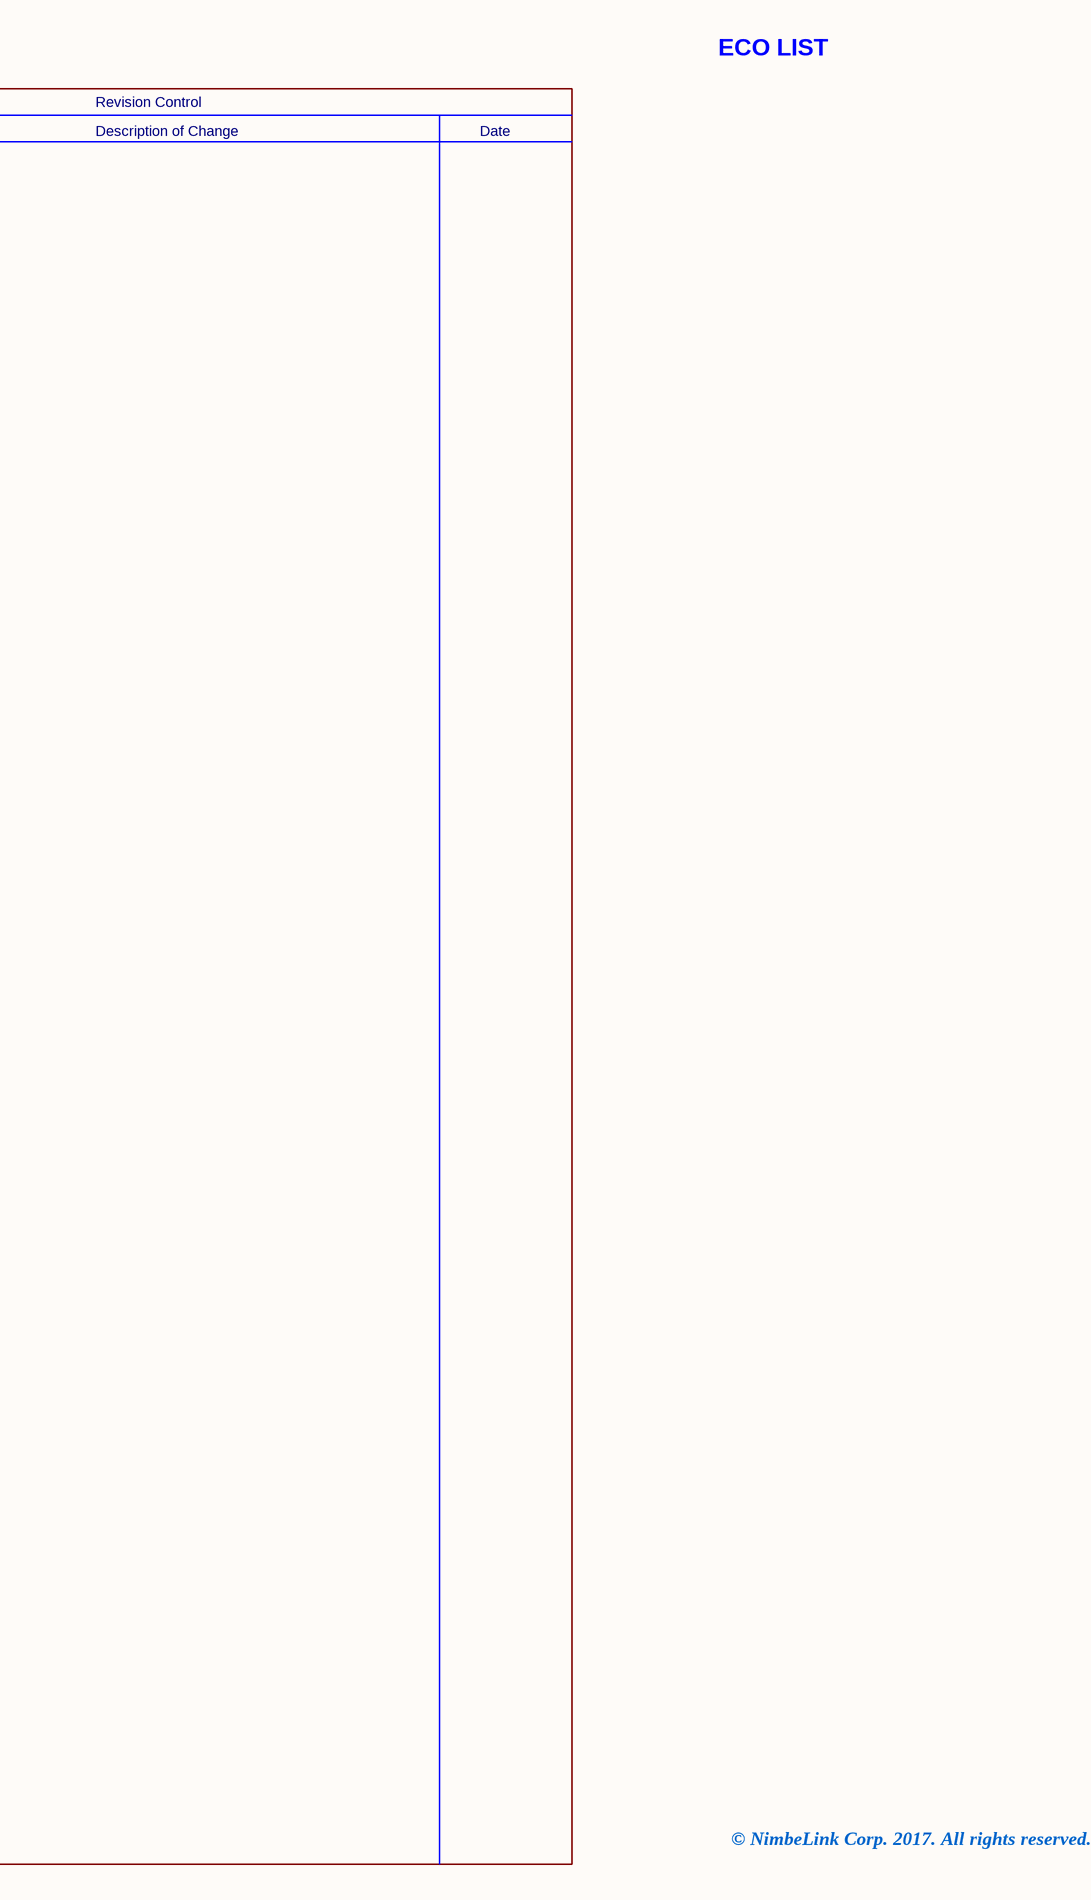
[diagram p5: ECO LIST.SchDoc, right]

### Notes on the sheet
- ECO LIST
- Assy Part Number
- Rev
- Description of Change
- Revision Control
- Date
- 1001386
- A
- Alpha Release
- 2017-03-16
- B
- SCH Changes:
  -NP R22
- 2017-05-15
- 1001430
- 2017-05-19
- SCH Changes:
  -Moved Skwyire RTS connection from J11-33 to J11-35.
  -Moved Skywire CTS connection from J11-23 to J11-33
  -Connected Skywire pin 13 (J101-3) to RPI headers GPIO12
  -Added R35 (NP).
  -Updated Memory Image PN
  -Updated PCB PN
  PCB Changes
  -Added 5V Silkscreen indicator near J5
  -Implemented SCH changes
- 1001502
- 2017-10-02
- SCH Changes:
  -Corrected J9/J10 to use correct pinout for Grove sensors
  -Updated PCB, SCH, and Memory PN's
  PCB Changes
  -Implemented SCH changes
- © NimbeLink Corp. 2017. All rights reserved.

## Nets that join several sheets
GND: Top (30 pins), Skywire (23 pins), Power (13 pins)
VCC_3V3: Top (18 pins), Power (R6.2 R9.2)
VCC_4V0: Skywire (5 pins), Power (5 pins)
VCC_5V0_Hat: Top (J8.2 J8.4 J11.4 J11.56), Power (D1.K)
